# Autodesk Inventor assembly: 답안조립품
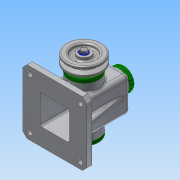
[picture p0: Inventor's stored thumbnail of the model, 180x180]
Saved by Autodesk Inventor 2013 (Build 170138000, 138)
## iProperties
Created: 2018-10
Part Number: 답안조립품
Document SubType Name: Assembly
Designer: Administrator
Author: Administrator
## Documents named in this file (14)
- C:\Users\Administrator\Desktop\481013V1006\답안조립품.iam
- C:\Users\Administrator\Desktop\481013V1006\본체.ipt
- C:\Users\Administrator\Desktop\481013V1006\V-벨트풀리.ipt
- C:\Users\Administrator\Desktop\481013V1006\뒤커버.ipt
- C:\Users\Administrator\Desktop\481013V1006\멈춤링 15 x 1.ipt
- C:\Users\Administrator\Desktop\481013V1006\베어링 15 x 35 x 11.ipt
- C:\Users\Administrator\Desktop\481013V1006\볼트 M4 x 10.ipt
- C:\Users\Administrator\Desktop\481013V1006\볼트 M6 x 12.ipt
- C:\Users\Administrator\Desktop\481013V1006\상부캡.ipt
- C:\Users\Administrator\Desktop\481013V1006\앞커버.ipt
- C:\Users\Administrator\Desktop\481013V1006\오일실 15 25 7.ipt
- C:\Users\Administrator\Desktop\481013V1006\와셔.ipt
- C:\Users\Administrator\Desktop\481013V1006\축.ipt
- C:\Users\Administrator\Desktop\481013V1006\키 5 x 5 x 14.ipt
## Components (1 placed, 1 different names)
1. V-벨트풀리:1
